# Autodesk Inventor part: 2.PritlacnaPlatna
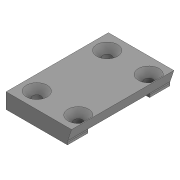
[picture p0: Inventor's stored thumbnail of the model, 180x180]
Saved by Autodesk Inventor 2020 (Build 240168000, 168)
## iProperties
Created: 2022-04
Part Number: 2.PritlacnaPlatna
Material: Generic
Document SubType Name: Modeling
Designer: marti
Density: 1 g/cm^3
Appearance: Default(2)
Author: marti
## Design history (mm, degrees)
sketch "Sketch1" dims "d48" = 10
  geometry: L1 (15, -25)-(-15, -25); L2 (-15, -25)-(-15, 25); L3 (-15, 25)-(15, 25); L4 (15, 25)-(15, -25); L5 (15, -25)-(-15, 25); L6 (-15, -25)-(15, 25); L7 (15, -15)-(-15, -15); L8 (-15, -15)-(-15, 15); L9 (-15, 15)-(15, 15); L10 (15, 15)-(15, -15); L11 (15, -15)-(-15, 15); L12 (-15, -15)-(15, 15); C1 r 2.05 at (-12.5, -17.2); C2 r 2.05 at (-12.5, 17.2); C3 r 2.05 at (7.8, -17.2); C4 r 2.05 at (7.8, 17.2); 1 further point
  constraints: 24 end point, 4 centre point, 4 midpoint, 4 parallel, 3 horizontal, 2 perpendicular, 1 point on line, 4 other
  dimensions: "d0" = 30 distance of L2.end L3.end; "d1" = 50 distance of L1.end L2.end; "d2" = 30 distance of L7.end L8.end; "d5" = 4.1 diameter of C1; "d6" = 4.1 diameter of C2 (= d5); "d15" = 2.5 distance from line of L2 C1.centre; "d16" = 2.5 distance from line of L2 C2.centre (= d15); "d17" = 2.2 distance from line of L7 C1.centre; "d18" = 2.2 distance from line of L9 C2.centre (= d17); "d45" = 20.3 distance of C1.centre C3.centre
extrude "Extrusion1" new body sketch "Sketch1" distance "d7" = 8; taper "d8" = 0 deg
sketch "Sketch5"
  geometry: L1 (-17.5, 15.1)-(17.5, 15.1); L2 (17.5, 15.1)-(17.5, -15.1); L3 (17.5, -15.1)-(-17.5, -15.1); L4 (-17.5, -15.1)-(-17.5, 15.1); L5 (-17.5, 15.1)-(17.5, -15.1); L6 (17.5, 15.1)-(-17.5, -15.1); 1 further point
  constraints: 12 end point, 2 midpoint, 2 parallel, 1 horizontal, 1 perpendicular
  dimensions: "d29" = 35 distance of L2.end L3.end; "d30" = 30.2 distance of L1.end L2.end
extrude "Extrusion5" cut sketch "Sketch5" distance "d31" = 2; taper "d32" = 0 deg
sketch "Sketch7"
  geometry: L1 (0, 8)-(30, 8) reference; L2 (30, 8)-(32, 8); L3 (30, 2)-(0, 2) reference; L4 (32, 8)-(30, 2); L5 (30, 0)-(30, 8) reference; L6 (30, 2)-(30, 8); 1 further point
  constraints: 6 end point, 1 horizontal, 1 perpendicular
  dimensions: "d35" = 2 distance of L1.end L2.end
extrude "Extrusion7" join sketch "Sketch7" distance "d36" = 50; taper "d37" = 0 deg
fillet "Fillet5" dims "d41" = 0.6
fillet "Fillet6" dims "d42" = 2.7
sketch "Sketch8"
  geometry: L1 (12.5, 17.2)-(-7.8, 17.2); L2 (12.5, -17.2)-(-7.8, -17.2); C1 r 2.05 at (12.5, 17.2) reference; C2 r 2.05 at (-7.8, 17.2); C3 r 2.05 at (12.5, -17.2) reference; C4 r 2.05 at (-7.8, -17.2); 1 further point
  constraints: 4 end point, 2 centre point, 2 coincident, 2 horizontal
  dimensions: "d50" = 20.3 distance of L1.start L1.end; "d51" = 4.1 diameter of C2; "d52" = 20.3 distance of L2.start L2.end; "d53" = 4.1 diameter of C4
extrude "Extrusion8" cut sketch "Sketch8" distance "d54" = 8; taper "d55" = 0 deg
chamfer "Chamfer3" distance "d56" = 3; stored, may be unused: second distance "d57" = 2, angle "d58" = 45 deg
sketch "Sketch9"
  geometry: L1 (0, 0)-(0, 2) reference; L2 (30, 1.562)-(30, 0) reference; L3 (0, 0)-(30, 0); L4 (30, 0)-(30, 0.5); L5 (30, 0.5)-(0, 0.5); L6 (0, 0.5)-(0, 0); 3 further points
  constraints: 8 end point, 2 parallel, 1 horizontal, 1 perpendicular, 1 point on line
  dimensions: "d60" = 0.5 distance of L4.end L3.end
extrude "Extrusion9" cut sketch "Sketch9" distance "d61" = 50; taper "d62" = 0 deg
sketch "Sketch10"
  geometry: L1 (32, 0)-(31.6, 0); L2 (32, 0)-(22.45, 0) reference; L3 (32, 0)-(30.137, -5.59) reference; L4 (32, 0)-(32, -1); L5 (32, -1)-(31.667, -1); L6 (31.667, -1)-(31.267, -1); L7 (31.267, -1)-(31.6, 0); L8 (32, 0)-(31.667, -1); 1 further point
  constraints: 12 end point, 3 point on line, 1 perpendicular, 1 vertical
  dimensions: "d63" = 0.4 distance of L1.start L1.end; "d64" = 1 distance of L1.start L4.end; "d65" = 0.4 distance of L5.end L6.end
extrude "Extrusion10" join sketch "Sketch10" distance "d66" = 50; taper "d67" = 0 deg
body "Solid1"
